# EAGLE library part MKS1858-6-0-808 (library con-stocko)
Serie MKS 1850 Lötstifte In-line, Raster 2.5 mm, Stiftwannen, stehend, mit Rastlasche Source: http://www.stocko.de/de/index.php?seite=ka_rfk2_mks1850.html&rubrik=Katalog+-+RFK+2 rfk_1850.pdf
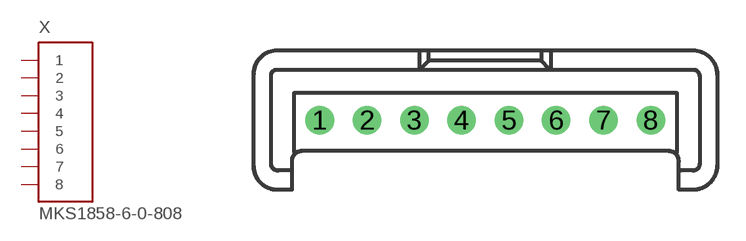
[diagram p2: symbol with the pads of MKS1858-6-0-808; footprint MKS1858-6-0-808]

Designator prefix X

## MKS1858-6-0-808 (OC_FARNELL: unknown; OC_NEWARK: unknown)  [MKS1858-6-0-808]
1  1  in
2  2  in
3  3  in
4  4  in
5  5  in
6  6  in
7  7  in
8  8  in

## Footprint MKS1858-6-0-808 (pad centres in mm)
Serie MKS 1850 Lötstifte In-line, Raster 2.5 mm, Stiftwannen, stehend, mit Rastlasche Source: http://www.stocko.de/de/index.php?seite=ka_rfk2_mks1850.html&rubrik=Katalog+-+RFK+2 rfk_1850.pdf
drill 1 pad 1.422 round: 1 -8.75,0; 2 -6.25,0; 3 -3.75,0; 4 -1.25,0; 5 1.25,0; 6 3.75,0; 7 6.25,0; 8 8.75,0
